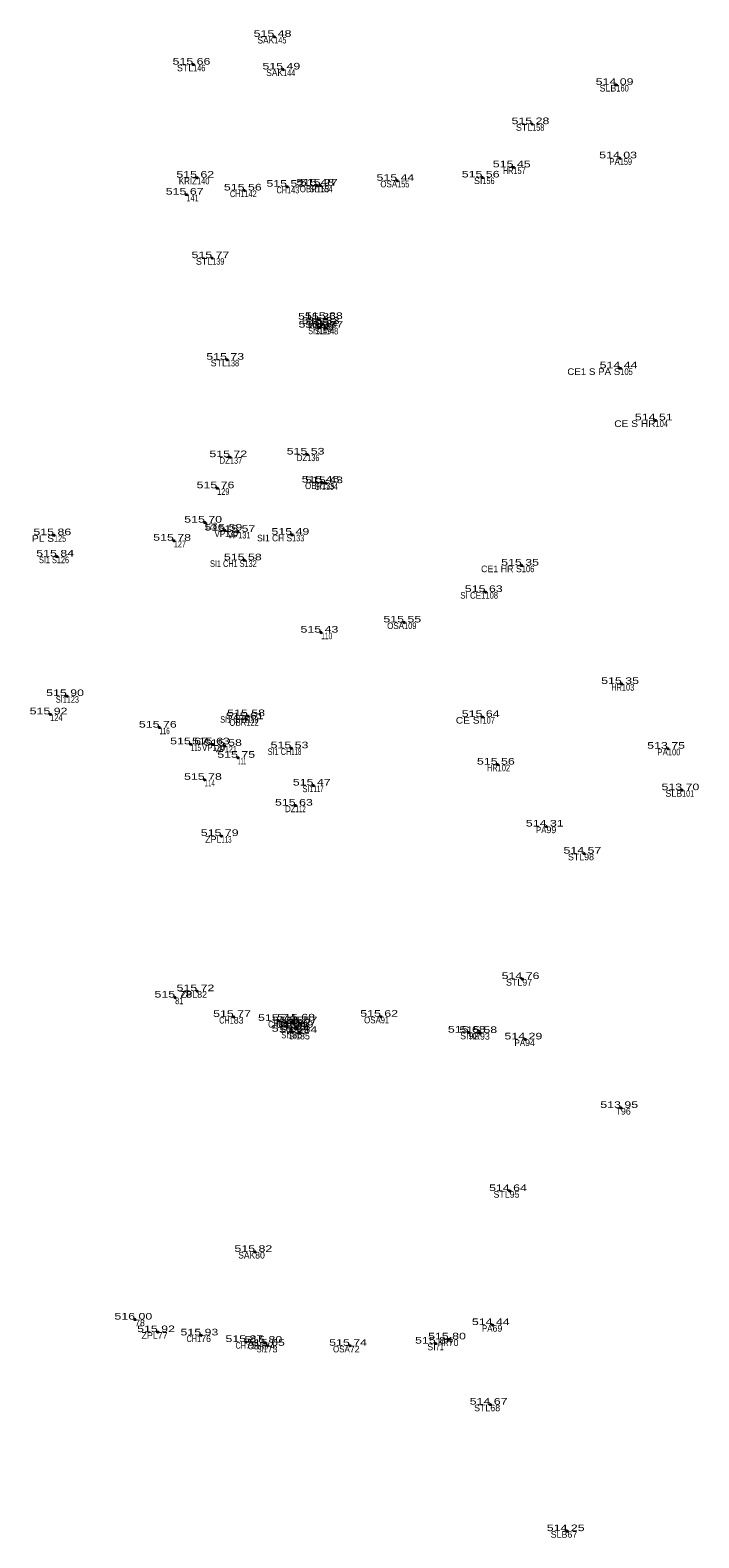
# Model space of a CAD drawing. Extents: x -643086 to -639283, y -1131805 to -1123269.
# Drawn here: x -639378.8 to -639348.4, y -1123773.8 to -1123705.4 of the extents above; entities that cross this region are included whole.
import ezdxf
from ezdxf.enums import TextEntityAlignment as Align

# ---------------------------------------------------------------- set-up
doc = ezdxf.new("R2010")
doc.units = 0
doc.header["$LTSCALE"] = 0.12
doc.header["$PDMODE"] = 32
doc.header["$PDSIZE"] = 0.06
for name, color, linetype in [('1', 7, 'Continuous'), ('2', 7, 'Continuous'), ('3', 7, 'Continuous'), ('4', 7, 'Continuous')]:
    doc.layers.add(name, color=color, linetype=linetype)

msp = doc.modelspace()

# ---------------------------------------------------------------- linework, layer by layer
at = {"layer": '1'}
for p in [(-639367.71, -1123705.7), (-639371.39, -1123706.96), (-639367.31, -1123707.18), (-639352.18, -1123707.88), (-639356, -1123709.66), (-639352.02, -1123711.21), (-639356.85, -1123711.62), (-639371.22, -1123712.09), (-639367.13, -1123712.5), (-639365.77, -1123712.45), (-639365.61, -1123712.45), (-639362.13, -1123712.23), (-639358.26, -1123712.08), (-639371.7, -1123712.86), (-639369.06, -1123712.67), (-639370.53, -1123715.74), (-639365.69, -1123718.53), (-639365.52, -1123718.72), (-639365.38, -1123718.5), (-639365.67, -1123718.89), (-639365.36, -1123718.9), (-639369.86, -1123720.35), (-639352, -1123720.74), (-639350.4, -1123723.1), (-639369.72, -1123724.77), (-639366.21, -1123724.65), (-639370.3, -1123726.18), (-639365.53, -1123725.92), (-639365.37, -1123725.95), (-639377.71, -1123728.31), (-639370.86, -1123727.74), (-639369.94, -1123728.1), (-639369.35, -1123728.16), (-639366.9, -1123728.29), (-639372.27, -1123728.56), (-639377.58, -1123729.28), (-639369.06, -1123729.45), (-639356.47, -1123729.69), (-639358.12, -1123730.89), (-639361.82, -1123732.27), (-639365.58, -1123732.73), (-639351.93, -1123735.06), (-639377.13, -1123735.61), (-639377.88, -1123736.44), (-639368.91, -1123736.52), (-639372.92, -1123737.04), (-639368.97, -1123736.66), (-639358.26, -1123736.56), (-639371.5, -1123737.8), (-639370.51, -1123737.8), (-639369.96, -1123737.87), (-639369.36, -1123738.41), (-639366.94, -1123737.98), (-639349.84, -1123738), (-639357.57, -1123738.72), (-639370.87, -1123739.41), (-639365.93, -1123739.67), (-639349.19, -1123739.88), (-639366.74, -1123740.58), (-639370.11, -1123741.96), (-639355.35, -1123741.53), (-639353.64, -1123742.76), (-639356.45, -1123748.45), (-639372.21, -1123749.29), (-639371.21, -1123749), (-639369.55, -1123750.17), (-639362.87, -1123750.16), (-639367.51, -1123750.35), (-639366.89, -1123750.84), (-639366.85, -1123750.46), (-639366.71, -1123750.66), (-639366.64, -1123750.33), (-639366.54, -1123750.89), (-639366.53, -1123750.46), (-639358.89, -1123750.88), (-639358.37, -1123750.9), (-639356.32, -1123751.19), (-639351.97, -1123754.3), (-639357.02, -1123758.07), (-639368.58, -1123760.83), (-639374.03, -1123763.9), (-639373, -1123764.47), (-639357.8, -1123764.15), (-639371.03, -1123764.62), (-639368.99, -1123764.92), (-639368.13, -1123764.95), (-639368.01, -1123765.09), (-639364.28, -1123765.09), (-639360.38, -1123764.99), (-639359.79, -1123764.8), (-639357.9, -1123767.76), (-639354.4, -1123773.5)]:
    msp.add_point(p, dxfattribs=at)

# ---------------------------------------------------------------- texts
at = {"layer": '2'}
for s, width, p in [('145', 0.8, (-639367.71, -1123706)), ('146', 0.8, (-639371.39, -1123707.26)), ('144', 0.8, (-639367.31, -1123707.48)), ('160', 0.85, (-639352.18, -1123708.18)), ('158', 0.8, (-639356, -1123709.96)), ('159', 0.8, (-639352.02, -1123711.51)), ('157', 0.8, (-639356.85, -1123711.92)), ('140', 0.85, (-639371.22, -1123712.39)), ('143', 0.8, (-639367.13, -1123712.8)), ('153', 0.8, (-639365.77, -1123712.75)), ('154', 0.8, (-639365.61, -1123712.75)), ('155', 0.8, (-639362.13, -1123712.53)), ('156', 0.8, (-639358.26, -1123712.38)), ('141', 0.7, (-639371.7, -1123713.16)), ('142', 0.8, (-639369.06, -1123712.97)), ('139', 0.8, (-639370.53, -1123716.04)), ('150', 0.85, (-639365.69, -1123718.83)), ('152', 0.8, (-639365.52, -1123719.02)), ('151', 0.7, (-639365.38, -1123718.8)), ('149', 0.8, (-639365.67, -1123719.19)), ('148', 0.8, (-639365.36, -1123719.2)), ('138', 0.8, (-639369.86, -1123720.65)), ('105', 0.85, (-639352, -1123721.04)), ('104', 0.85, (-639350.4, -1123723.4)), ('137', 0.8, (-639369.72, -1123725.07)), ('136', 0.8, (-639366.21, -1123724.95)), ('129', 0.8, (-639370.3, -1123726.48)), ('135', 0.8, (-639365.53, -1123726.22)), ('134', 0.8, (-639365.37, -1123726.25)), ('125', 0.8, (-639377.71, -1123728.61)), ('128', 0.8, (-639370.86, -1123728.04)), ('130', 0.85, (-639369.94, -1123728.4)), ('131', 0.7, (-639369.35, -1123728.46)), ('133', 0.8, (-639366.9, -1123728.59)), ('127', 0.8, (-639372.27, -1123728.86)), ('126', 0.8, (-639377.58, -1123729.58)), ('132', 0.8, (-639369.06, -1123729.75)), ('106', 0.85, (-639356.47, -1123729.99)), ('108', 0.85, (-639358.12, -1123731.19)), ('109', 0.85, (-639361.82, -1123732.57)), ('110', 0.6, (-639365.58, -1123733.03)), ('103', 0.85, (-639351.93, -1123735.36)), ('123', 0.8, (-639377.13, -1123735.91)), ('124', 0.8, (-639377.88, -1123736.74)), ('119', 0.55, (-639368.91, -1123736.82)), ('116', 0.55, (-639372.92, -1123737.34)), ('122', 0.8, (-639368.97, -1123736.96)), ('107', 0.85, (-639358.26, -1123736.86)), ('115', 0.55, (-639371.5, -1123738.1)), ('120', 0.85, (-639370.51, -1123738.1)), ('121', 0.7, (-639369.96, -1123738.17)), ('111', 0.45, (-639369.36, -1123738.71)), ('118', 0.55, (-639366.94, -1123738.28)), ('100', 0.85, (-639349.84, -1123738.3)), ('102', 0.85, (-639357.57, -1123739.02)), ('114', 0.55, (-639370.87, -1123739.71)), ('117', 0.55, (-639365.93, -1123739.97)), ('101', 0.75, (-639349.19, -1123740.18)), ('112', 0.55, (-639366.74, -1123740.88)), ('113', 0.55, (-639370.11, -1123742.26)), ('81', 0.8, (-639372.21, -1123749.59)), ('91', 0.8, (-639362.87, -1123750.46)), ('71', 0.8, (-639360.38, -1123765.29))]:
    msp.add_text(s, height=0.3, dxfattribs=dict(at, width=width)).set_placement(p)
for s, p in [('99', (-639355.35, -1123741.83)), ('98', (-639353.64, -1123743.06)), ('97', (-639356.45, -1123748.75)), ('82', (-639371.21, -1123749.3)), ('83', (-639369.55, -1123750.47)), ('84', (-639367.51, -1123750.65)), ('86', (-639366.89, -1123751.14)), ('87', (-639366.85, -1123750.76)), ('90', (-639366.71, -1123750.96)), ('89', (-639366.64, -1123750.63)), ('88', (-639366.53, -1123750.76)), ('92', (-639358.89, -1123751.18)), ('85', (-639366.54, -1123751.19)), ('93', (-639358.37, -1123751.2)), ('94', (-639356.32, -1123751.49)), ('96', (-639351.97, -1123754.6)), ('95', (-639357.02, -1123758.37)), ('80', (-639368.58, -1123761.13)), ('78', (-639374.03, -1123764.2)), ('77', (-639373, -1123764.77)), ('69', (-639357.8, -1123764.45)), ('76', (-639371.03, -1123764.92)), ('75', (-639368.99, -1123765.22)), ('74', (-639368.13, -1123765.25)), ('73', (-639368.01, -1123765.39)), ('72', (-639364.28, -1123765.39)), ('70', (-639359.79, -1123765.1)), ('68', (-639357.9, -1123768.06)), ('67', (-639354.4, -1123773.8))]:
    msp.add_text(s, height=0.3, dxfattribs=at).set_placement(p)
at = {"layer": '3', "width": 1.4}
for s, p in [('515 48 ', (-639367.71, -1123705.7)), ('515 66 ', (-639371.39, -1123706.96)), ('515 49 ', (-639367.31, -1123707.18)), ('514 09 ', (-639352.18, -1123707.88)), ('515 28 ', (-639356, -1123709.66)), ('514 03 ', (-639352.02, -1123711.21)), ('515 62 ', (-639371.22, -1123712.09)), ('515 56 ', (-639358.26, -1123712.08)), ('515 45 ', (-639356.85, -1123711.62)), ('515 67 ', (-639371.7, -1123712.86)), ('515 56 ', (-639369.06, -1123712.67)), ('515 52 ', (-639367.13, -1123712.5)), ('515 48 ', (-639365.77, -1123712.45)), ('515 27 ', (-639365.61, -1123712.45)), ('515 44 ', (-639362.13, -1123712.23)), ('515 77 ', (-639370.53, -1123715.74)), ('515 36 ', (-639365.69, -1123718.53)), ('515 37 ', (-639365.67, -1123718.89)), ('515 33 ', (-639365.52, -1123718.72)), ('515 38 ', (-639365.38, -1123718.5)), ('515 37 ', (-639365.36, -1123718.9)), ('515 73 ', (-639369.86, -1123720.35)), ('514 44 ', (-639352, -1123720.74)), ('514 51 ', (-639350.4, -1123723.1)), ('515 72 ', (-639369.72, -1123724.77)), ('515 53 ', (-639366.21, -1123724.65)), ('515 76 ', (-639370.3, -1123726.18)), ('515 45 ', (-639365.53, -1123725.92)), ('515 43 ', (-639365.37, -1123725.95)), ('515 70 ', (-639370.86, -1123727.74)), ('515 86 ', (-639377.71, -1123728.31)), ('515 78 ', (-639372.27, -1123728.56)), ('515 59 ', (-639369.94, -1123728.1)), ('515 57 ', (-639369.35, -1123728.16)), ('515 49 ', (-639366.9, -1123728.29)), ('515 84 ', (-639377.58, -1123729.28)), ('515 58 ', (-639369.06, -1123729.45)), ('515 35 ', (-639356.47, -1123729.69)), ('515 63 ', (-639358.12, -1123730.89)), ('515 55 ', (-639361.82, -1123732.27)), ('515 43 ', (-639365.58, -1123732.73)), ('515 35 ', (-639351.93, -1123735.06)), ('515 90 ', (-639377.13, -1123735.61)), ('515 92 ', (-639377.88, -1123736.44)), ('515 61 ', (-639368.97, -1123736.66)), ('515 58 ', (-639368.91, -1123736.52)), ('515 64 ', (-639358.26, -1123736.56)), ('515 76 ', (-639372.92, -1123737.04)), ('515 67 ', (-639371.5, -1123737.8)), ('515 63 ', (-639370.51, -1123737.8)), ('515 58 ', (-639369.96, -1123737.87)), ('515 53 ', (-639366.94, -1123737.98)), ('513 75 ', (-639349.84, -1123738)), ('515 75 ', (-639369.36, -1123738.41)), ('515 56 ', (-639357.57, -1123738.72)), ('515 78 ', (-639370.87, -1123739.41)), ('515 47 ', (-639365.93, -1123739.67)), ('513 70 ', (-639349.19, -1123739.88)), ('515 63 ', (-639366.74, -1123740.58)), ('514 31 ', (-639355.35, -1123741.53)), ('515 79 ', (-639370.11, -1123741.96)), ('514 57 ', (-639353.64, -1123742.76)), ('514 76 ', (-639356.45, -1123748.45)), ('515 72 ', (-639371.21, -1123749)), ('515 78 ', (-639372.21, -1123749.29)), ('515 77 ', (-639369.55, -1123750.17)), ('515 74 ', (-639367.51, -1123750.35)), ('515 55 ', (-639366.85, -1123750.46)), ('515 68 ', (-639366.64, -1123750.33)), ('515 57 ', (-639366.53, -1123750.46)), ('515 62 ', (-639362.87, -1123750.16)), ('515 54 ', (-639366.89, -1123750.84)), ('515 49 ', (-639366.71, -1123750.66)), ('515 54 ', (-639366.54, -1123750.89)), ('515 68 ', (-639358.89, -1123750.88)), ('515 58 ', (-639358.37, -1123750.9)), ('514 29 ', (-639356.32, -1123751.19)), ('513 95 ', (-639351.97, -1123754.3)), ('514 64 ', (-639357.02, -1123758.07)), ('515 82 ', (-639368.58, -1123760.83)), ('516 00 ', (-639374.03, -1123763.9)), ('514 44 ', (-639357.8, -1123764.15)), ('515 92 ', (-639373, -1123764.47)), ('515 93 ', (-639371.03, -1123764.62)), ('515 80 ', (-639359.79, -1123764.8)), ('515 87 ', (-639368.99, -1123764.92)), ('515 80 ', (-639368.13, -1123764.95)), ('515 65 ', (-639368.01, -1123765.09)), ('515 74 ', (-639364.28, -1123765.09)), ('515 84 ', (-639360.38, -1123764.99)), ('514 67 ', (-639357.9, -1123767.76)), ('514 25 ', (-639354.4, -1123773.5))]:
    msp.add_text(s, height=0.3, dxfattribs=at).set_placement(p, align=Align.CENTER)
at = {"layer": '4'}
for s, width, p in [('SAK', 0.95, (-639367.71, -1123706)), ('SAK', 0.95, (-639367.31, -1123707.48)), ('HR', 0.8, (-639356.85, -1123711.92)), ('PA', 0.9, (-639352.02, -1123711.51)), ('KRIZ', 0.9, (-639371.22, -1123712.39)), ('CH', 0.8, (-639367.13, -1123712.8)), ('OBR', 0.9, (-639365.77, -1123712.75)), ('SI1', 0.8, (-639365.61, -1123712.75)), ('OSA', 0.9, (-639362.13, -1123712.53)), ('CH1', 0.8, (-639369.06, -1123712.97)), ('SI1', 0.8, (-639365.69, -1123718.83)), ('VP', 0.9, (-639365.52, -1123719.02)), ('SI1', 0.8, (-639365.38, -1123718.8)), ('SI1', 0.8, (-639365.67, -1123719.19)), ('SI1', 0.8, (-639365.36, -1123719.2)), ('CE1 S PA S', 1.1, (-639352, -1123721.04)), ('CE S HR', 1.15, (-639350.4, -1123723.4)), ('DZ', 0.9, (-639369.72, -1123725.07)), ('DZ', 0.9, (-639366.21, -1123724.95)), ('OBR', 0.9, (-639365.53, -1123726.22)), ('SI1', 0.8, (-639365.37, -1123726.25)), ('PL S', 1.15, (-639377.71, -1123728.61)), ('VP', 0.9, (-639369.94, -1123728.4)), ('VP', 0.9, (-639369.35, -1123728.46)), ('SI1 CH S', 0.95, (-639366.9, -1123728.59)), ('SI1 S', 0.8, (-639377.58, -1123729.58)), ('SI1 CH1 S', 0.8, (-639369.06, -1123729.75)), ('SI CE1', 0.9, (-639358.12, -1123731.19)), ('OSA', 0.9, (-639361.82, -1123732.57)), ('HR', 0.8, (-639351.93, -1123735.36)), ('SI1', 0.8, (-639377.13, -1123735.91)), ('SI1 CH1', 0.8, (-639368.91, -1123736.82)), ('OBR', 0.9, (-639368.97, -1123736.96)), ('CE SI', 1.15, (-639358.26, -1123736.86)), ('VP', 0.9, (-639370.51, -1123738.1)), ('VP', 0.9, (-639369.96, -1123738.17)), ('SI1 CH', 0.8, (-639366.94, -1123738.28)), ('PA', 0.9, (-639349.84, -1123738.3)), ('HR', 0.8, (-639357.57, -1123739.02)), ('SI1', 0.8, (-639365.93, -1123739.97)), ('DZ', 0.9, (-639366.74, -1123740.88)), ('PA', 0.9, (-639355.35, -1123741.83)), ('CH1', 0.8, (-639369.55, -1123750.47)), ('OSA', 0.9, (-639362.87, -1123750.46)), ('CH', 0.8, (-639367.51, -1123750.65)), ('OBR', 0.9, (-639366.64, -1123750.63)), ('SI1', 0.8, (-639366.89, -1123751.14)), ('SI1', 0.8, (-639366.85, -1123750.76)), ('VP', 0.9, (-639366.71, -1123750.96)), ('SI1', 0.8, (-639366.53, -1123750.76)), ('SI1', 0.8, (-639366.54, -1123751.19)), ('HR', 0.8, (-639358.37, -1123751.2)), ('PA', 0.9, (-639356.32, -1123751.49)), ('T', 0.8, (-639351.97, -1123754.6)), ('SAK', 0.95, (-639368.58, -1123761.13)), ('PA', 0.9, (-639357.8, -1123764.45)), ('CH1', 0.8, (-639371.03, -1123764.92)), ('CH', 0.8, (-639368.99, -1123765.22)), ('OBR', 0.9, (-639368.13, -1123765.25)), ('SI1', 0.8, (-639368.01, -1123765.39)), ('OSA', 0.9, (-639364.28, -1123765.39)), ('HR', 0.8, (-639359.79, -1123765.1))]:
    msp.add_text(s, height=0.3, dxfattribs=dict(at, width=width)).set_placement(p, align=Align.RIGHT)
for s, p in [('STL', (-639371.39, -1123707.26)), ('SLB', (-639352.18, -1123708.18)), ('STL', (-639356, -1123709.96)), ('SI', (-639358.26, -1123712.38)), ('STL', (-639370.53, -1123716.04)), ('STL', (-639369.86, -1123720.65)), ('CE1 HR S', (-639356.47, -1123729.99)), ('SLB', (-639349.19, -1123740.18)), ('ZPL', (-639370.11, -1123742.26)), ('STL', (-639353.64, -1123743.06)), ('STL', (-639356.45, -1123748.75)), ('ZPL', (-639371.21, -1123749.3)), ('SI', (-639358.89, -1123751.18)), ('STL', (-639357.02, -1123758.37)), ('ZPL', (-639373, -1123764.77)), ('SI', (-639360.38, -1123765.29)), ('STL', (-639357.9, -1123768.06)), ('SLB', (-639354.4, -1123773.8))]:
    msp.add_text(s, height=0.3, dxfattribs=at).set_placement(p, align=Align.RIGHT)

doc.saveas('drawing.dxf')
